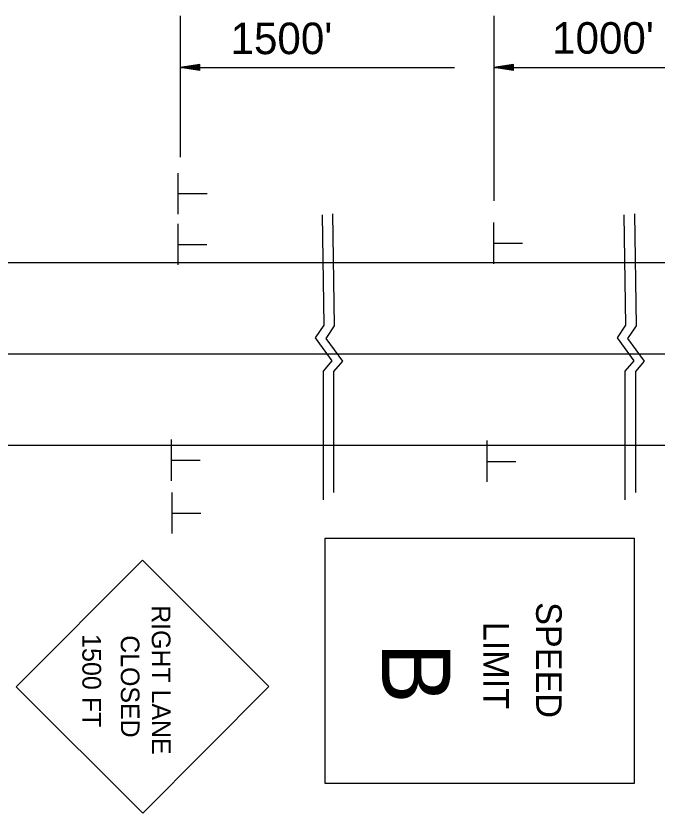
# Model space of a CAD drawing. Extents: x 13528 to 25043, y 7635 to 10612.
# Drawn here: x 16174.9 to 16296.9, y 10206.7 to 10358.4 of the extents above; entities that cross this region are included whole.
import ezdxf

# ---------------------------------------------------------------- set-up
doc = ezdxf.new("R2010")
doc.units = 0
doc.layers.add('Default', color=7, linetype='Continuous')

msp = doc.modelspace()

# ---------------------------------------------------------------- linework, layer by layer
at = {"layer": 'Default'}
for p, q in [((16206.16, 10358.39), (16206.16, 10331.54)), ((16265.85, 10358.39), (16265.85, 10323.18)), ((16209.91, 10349.16), (16206.16, 10348.6)), ((16209.91, 10349.07), (16206.78, 10348.6)), ((16209.91, 10348.97), (16207.43, 10348.6)), ((16209.91, 10348.88), (16208.05, 10348.6)), ((16209.91, 10348.78), (16208.69, 10348.6)), ((16209.91, 10348.69), (16209.31, 10348.6)), ((16209.91, 10348.04), (16209.91, 10349.16)), ((16269.6, 10349.16), (16265.85, 10348.6)), ((16269.6, 10349.07), (16266.47, 10348.6)), ((16269.6, 10348.97), (16267.12, 10348.6)), ((16269.6, 10348.88), (16267.74, 10348.6)), ((16269.6, 10348.78), (16268.38, 10348.6)), ((16269.6, 10348.69), (16269.01, 10348.6)), ((16269.6, 10348.04), (16269.6, 10349.16)), ((16206.16, 10348.6), (16258.35, 10348.6)), ((16209.91, 10348.04), (16206.16, 10348.6)), ((16209.91, 10348.13), (16206.78, 10348.6)), ((16209.91, 10348.23), (16207.43, 10348.6)), ((16209.91, 10348.32), (16208.05, 10348.6)), ((16209.91, 10348.42), (16208.69, 10348.6)), ((16209.91, 10348.51), (16209.31, 10348.6)), ((16265.85, 10348.6), (16318.04, 10348.6)), ((16269.6, 10348.04), (16265.85, 10348.6)), ((16269.6, 10348.13), (16266.47, 10348.6)), ((16269.6, 10348.23), (16267.12, 10348.6)), ((16269.6, 10348.32), (16267.74, 10348.6)), ((16269.6, 10348.42), (16268.38, 10348.6)), ((16269.6, 10348.51), (16269.01, 10348.6)), ((16205.79, 10320.68), (16205.79, 10328.5)), ((16205.91, 10324.57), (16211.25, 10324.57)), ((16205.77, 10311.02), (16205.77, 10318.85)), ((16265.85, 10311.23), (16265.85, 10319.06)), ((16205.89, 10314.91), (16211.23, 10314.91)), ((16265.96, 10315.12), (16271.3, 10315.12)), ((16143.31, 10311.48), (16229.91, 10311.48)), ((16229.91, 10311.48), (16389.83, 10311.48)), ((16143.31, 10294.1), (16229.91, 10294.1)), ((16229.91, 10294.1), (16389.83, 10294.1)), ((16204.51, 10269.95), (16204.51, 10277.78)), ((16264.59, 10269.74), (16264.59, 10277.57)), ((16143.31, 10276.71), (16239.09, 10276.71)), ((16229.91, 10276.71), (16389.83, 10276.71)), ((16204.63, 10273.85), (16209.97, 10273.85)), ((16264.7, 10273.63), (16270.04, 10273.63)), ((16204.6, 10259.9), (16204.6, 10267.73)), ((16204.71, 10263.79), (16210.05, 10263.79)), ((16174.93, 10230.71), (16198.94, 10254.81)), ((16223.02, 10230.8), (16198.94, 10254.81)), ((16199.03, 10206.7), (16174.93, 10230.71)), ((16199.03, 10206.7), (16223.02, 10230.8))]:
    msp.add_line(p, q, dxfattribs=at)
for points in [[(16233.16, 10320.56), (16233.48, 10299.52), (16231.85, 10297.11), (16235.02, 10292.78), (16233.35, 10290.78), (16233.35, 10266.32)], [(16235.15, 10320.75), (16235.48, 10299.44), (16233.85, 10297.03), (16237.02, 10292.7), (16235.35, 10290.7), (16235.35, 10267.73)], [(16290.62, 10320.56), (16290.94, 10299.52), (16289.31, 10297.11), (16292.48, 10292.78), (16290.81, 10290.78), (16290.81, 10266.32)], [(16292.61, 10320.75), (16292.93, 10299.44), (16291.31, 10297.03), (16294.48, 10292.7), (16292.81, 10290.7), (16292.81, 10267.73)]]:
    msp.add_lwpolyline(points, dxfattribs=at)
msp.add_lwpolyline([(16292.59, 10212.29), (16233.72, 10212.29), (16233.72, 10259), (16292.59, 10259)], close=True, dxfattribs=at)

# ---------------------------------------------------------------- texts
for s, p in [("1500'", (16215.73, 10351.12)), ("1000'", (16276.95, 10351.21))]:
    msp.add_text(s, height=6, dxfattribs=at).set_placement(p)
for s, height, rotation, p in [('RIGHT LANE', 3.544, 270.1004, (16200.73, 10246.25)), ('SPEED', 4.865, 270, (16273.91, 10246.84)), ('LIMIT', 4.865, 270, (16263.86, 10243.11)), ('1500 FT', 3.567, 270.0006, (16187.52, 10240.76)), ('CLOSED', 3.543, 270.1003, (16194.83, 10240.53)), ('B', 13.04, 270, (16244.56, 10239.18))]:
    msp.add_text(s, height=height, rotation=rotation, dxfattribs=at).set_placement(p)

doc.saveas('drawing.dxf')
